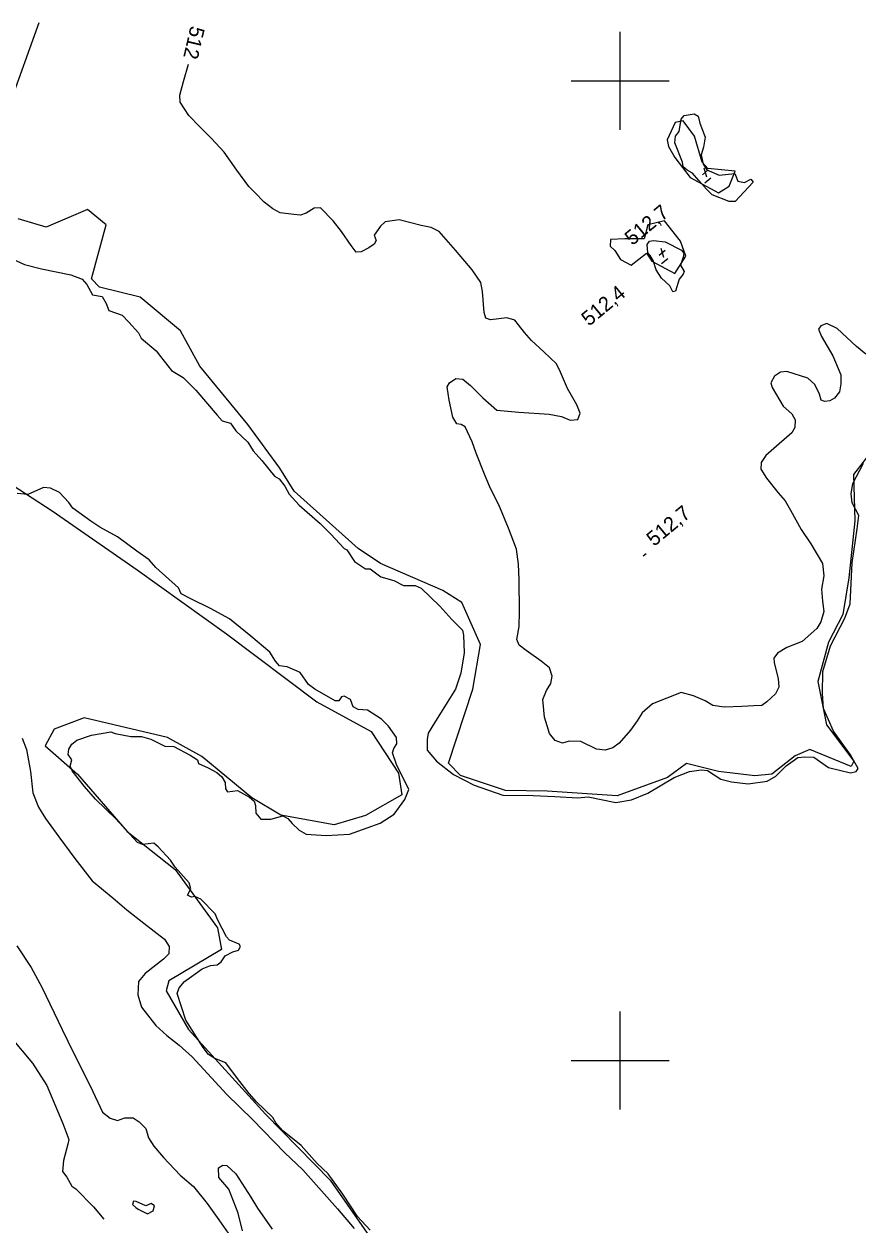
# Model space of a CAD drawing. Extents: x 347059 to 352153, y 6073752 to 6078601.
# Drawn here: x 350217.4 to 350472.8, y 6075549.6 to 6075917.4 of the extents above; entities that cross this region are included whole.
import ezdxf

# ---------------------------------------------------------------- set-up
doc = ezdxf.new("R2010")
doc.units = 0
for name, color, linetype in [('Level 2', 7, 'Continuous'), ('Level 3', 7, 'Continuous'), ('Level 4', 7, 'Continuous'), ('Level 44', 7, 'Continuous'), ('Level 61', 7, 'Continuous')]:
    doc.layers.add(name, color=color, linetype=linetype)

msp = doc.modelspace()

# ---------------------------------------------------------------- linework, layer by layer
at = {"layer": 'Level 2'}
for points in [[(350376.66, 6075817.02), (350372.8, 6075820.49), (350370.67, 6075822.86), (350368.9, 6075825.27), (350367.7, 6075826.69), (350365.29, 6075827.34), (350362.8, 6075827.12), (350360.3, 6075826.75), (350358.82, 6075827.25), (350358.3, 6075828.97), (350357.87, 6075835.49), (350357.29, 6075838.23), (350354.7, 6075842.1), (350349.51, 6075848.09), (350344.58, 6075853.77), (350342.06, 6075855.01), (350338.99, 6075855.64), (350332.3, 6075857.4), (350328.03, 6075856.75), (350326.62, 6075855.42), (350324.66, 6075852.67), (350325.25, 6075851.02), (350324.66, 6075849.98), (350322.97, 6075848.81), (350320.69, 6075847.55), (350319.16, 6075847.47), (350317.57, 6075849.5), (350314.64, 6075853.77), (350312.07, 6075857.13), (350308.24, 6075861.04), (350306.27, 6075860.99), (350303.82, 6075859.45), (350302.1, 6075858.8), (350300.08, 6075858.98), (350295.9, 6075859.49), (350293.6, 6075860.79), (350290.93, 6075862.84), (350287.97, 6075865.87), (350286.22, 6075867.63), (350282.54, 6075872.62), (350278.69, 6075878.14), (350274.79, 6075882.27), (350271.22, 6075885.87), (350267.93, 6075889.29), (350265.2, 6075893.47), (350265.15, 6075895.59), (350266.29, 6075899.79), (350267.82, 6075905.04)], [(350475.26, 6075816.21), (350472.34, 6075818.57), (350466.48, 6075824.1), (350463.27, 6075825.69), (350461.48, 6075824.98), (350460.74, 6075823.95), (350461.64, 6075821.62), (350465.09, 6075815.79), (350467.6, 6075809.97), (350467.59, 6075807.13), (350467.19, 6075804.76), (350465.66, 6075802.79), (350464.21, 6075801.97), (350462.68, 6075801.74), (350461.55, 6075802.13), (350461.04, 6075803.99), (350459.61, 6075806.95), (350457.45, 6075808.89), (350451.02, 6075810.97), (350449.05, 6075810.78), (350447.29, 6075809.55), (350446.11, 6075807.47), (350446.5, 6075806.06), (350449.96, 6075800.37), (350452.6, 6075798.03), (350453.54, 6075796.13), (350453.5, 6075793.81), (350452.58, 6075792.21), (350448.68, 6075788.77), (350444.56, 6075785.27), (350443.16, 6075783.13), (350443.07, 6075781.03), (350444.81, 6075778.33), (350448.36, 6075773.8), (350450.56, 6075771.36), (350452.15, 6075768.53), (350455.44, 6075762.57), (350458.35, 6075758.17), (350462, 6075752.11), (350462.35, 6075748.36), (350461.67, 6075744.28), (350461.96, 6075740.61), (350462.36, 6075737.45), (350461.45, 6075734.26), (350460.21, 6075732.25), (350455.69, 6075728.28), (350451.06, 6075726.49), (350448.17, 6075724.71), (350447.03, 6075723.2), (350447.2, 6075721.73), (350448.42, 6075716.97), (350448.57, 6075714.26), (350447.61, 6075712.24), (350444.88, 6075709.78), (350443.42, 6075708.67), (350440.95, 6075708.59)], [(350440.95, 6075708.59), (350437.24, 6075708.4), (350431.85, 6075708.13), (350428.34, 6075708.65), (350426.06, 6075710.09), (350422.49, 6075711.63), (350418.72, 6075712.61), (350409.89, 6075709.15), (350406.71, 6075706.43), (350405.2, 6075703.94), (350403.17, 6075701.13), (350399.73, 6075697.13), (350397.73, 6075695.7), (350395.36, 6075695.03), (350392.7, 6075695.33), (350387.95, 6075697.63), (350384.4, 6075697.72), (350382.32, 6075697.17), (350380.06, 6075697.94), (350378.35, 6075700.13), (350377.59, 6075702.45), (350376.85, 6075705.06), (350376.27, 6075710.5), (350377.43, 6075713.24), (350378.77, 6075715.46), (350379.16, 6075717.68), (350378.35, 6075720.23), (350375.82, 6075722.27), (350371.22, 6075725.5), (350369.02, 6075727.15), (350368.36, 6075728.88), (350369.04, 6075732.83), (350369.11, 6075737.34), (350369.02, 6075747.25), (350368.89, 6075752), (350368.24, 6075756.57), (350365.77, 6075762.98), (350362.78, 6075770.15), (350360.14, 6075775.34), (350358.45, 6075779.56), (350355.9, 6075785.9), (350354.65, 6075789.44), (350352.55, 6075793.99), (350351.29, 6075794.68), (350350.01, 6075794.94), (350348.79, 6075797.01), (350347.61, 6075802.21), (350346.99, 6075806.28), (350347.67, 6075807.53), (350349.66, 6075808.81), (350351.82, 6075808.62), (350354.13, 6075806.67), (350357.9, 6075802.85), (350362.25, 6075799.12), (350368.95, 6075798.46), (350378.27, 6075797.87), (350382.06, 6075797.18), (350384.65, 6075796.01), (350386.99, 6075796.24), (350387.73, 6075798.22), (350386.69, 6075800.71), (350383.9, 6075805.76), (350381.68, 6075810.76), (350380.44, 6075813.34), (350376.66, 6075817.02)], [(350216.8, 6075698.66), (350218.21, 6075695.25)], [(350218.21, 6075695.25), (350219.35, 6075688.51), (350220.06, 6075681.96), (350221.82, 6075677.5), (350224.03, 6075674.1), (350228.1, 6075668.5), (350232.96, 6075661.82), (350238.32, 6075655.01), (350244.6, 6075649.81), (350248.9, 6075646.16), (350254.11, 6075642.07), (350260.41, 6075637.16), (350261.83, 6075634.85), (350261.72, 6075632.6), (350260.14, 6075630.98), (350254.48, 6075626.58), (350252.47, 6075624.19), (350252.21, 6075620.06), (350253.37, 6075616.31), (350257.73, 6075610.69), (350261.12, 6075607.64), (350264.96, 6075604.69), (350268.9, 6075601.14), (350279.48, 6075589.61), (350287.38, 6075581.87), (350297.33, 6075571.7), (350302.81, 6075566.5), (350313.42, 6075554.6), (350318.53, 6075548.56)], [(350215.22, 6075635.1), (350219.64, 6075628.46), (350222.87, 6075622.43), (350229.11, 6075609.51), (350232.54, 6075602.3), (350237.76, 6075592.03), (350241.49, 6075584.14), (350243.74, 6075582.28), (350246.02, 6075581.65), (350248.33, 6075582.4), (350250.88, 6075582.4), (350252.67, 6075581.23), (350254.69, 6075579.17), (350255.55, 6075576.26), (350257.16, 6075573.72), (350260.09, 6075570.27), (350265.18, 6075564.89), (350269.34, 6075561.41), (350273.5, 6075556.18), (350277.09, 6075551.15), (350280.61, 6075546.05)], [(350213.2, 6075607.34), (350220.03, 6075599.13), (350224.35, 6075592.29), (350229.24, 6075580.68), (350231.1, 6075575.79), (350230.84, 6075574.36), (350229.5, 6075569.31), (350229.23, 6075565.98), (350230.47, 6075564.21), (350232.07, 6075561.53), (350233.31, 6075560.7), (350238.68, 6075555.15), (350241.87, 6075551.38)], [(350284.33, 6075547.82), (350282.99, 6075553.24), (350280.14, 6075560.58), (350277.06, 6075564.11), (350276.97, 6075567.12), (350278.32, 6075567.95), (350279.57, 6075567.79), (350282.25, 6075565.28), (350286.88, 6075558.15), (350288.95, 6075554.75), (350293.39, 6075548.3)], [(350252.38, 6075554.5), (350255.24, 6075553.04), (350256.96, 6075553.95), (350257.35, 6075555.48), (350256.35, 6075556.23), (350254.69, 6075555.52), (350251.78, 6075556.85), (350250.97, 6075556.93), (350250.63, 6075555.89), (350251.65, 6075554.93), (350252.38, 6075554.5)]]:
    msp.add_lwpolyline(points, dxfattribs=at)
at = {"layer": 'Level 3'}
for p, q in [((350425.17, 6075871.21), (350426.98, 6075872.7)), ((350425.63, 6075873.34), (350426.46, 6075870.59)), ((350425.89, 6075868.69), (350427.74, 6075870.22)), ((350412.43, 6075848.7), (350413.26, 6075845.95)), ((350411.97, 6075846.57), (350413.78, 6075848.06)), ((350412.69, 6075844.05), (350414.54, 6075845.58)), ((350407.02, 6075754.5), (350407.94, 6075755.27))]:
    msp.add_line(p, q, dxfattribs=at)
at = {"layer": 'Level 4'}
for points in [[(350419.29, 6075873.62), (350419.13, 6075875.01), (350416.77, 6075881.02), (350416.95, 6075883), (350418.08, 6075884.48), (350418.68, 6075888.25), (350419.61, 6075889.33), (350422.62, 6075889.8), (350423.88, 6075889.1), (350424.38, 6075887.01), (350426.04, 6075882.69), (350425.54, 6075879.61), (350424.82, 6075877.26), (350425.42, 6075874.42), (350426.5, 6075872.73), (350430.34, 6075871.08), (350435.13, 6075871.59), (350435.98, 6075869.26), (350438.04, 6075868.86), (350440.03, 6075869.84), (350440.77, 6075868.93), (350435.22, 6075863.01), (350433.33, 6075863.02), (350428.17, 6075865.08), (350426.47, 6075866.78), (350424.08, 6075869.42), (350422.12, 6075871.73), (350420.47, 6075872.63), (350419.29, 6075873.62)], [(350205.01, 6075849.43), (350217.55, 6075843.67), (350222.72, 6075842.35), (350231.69, 6075840.55), (350235.25, 6075839.26), (350236.63, 6075837.59), (350238.41, 6075834.43), (350241.38, 6075833.94), (350242.55, 6075831.79), (350243.39, 6075829.67), (350247.51, 6075828.16), (350249.46, 6075826.06), (350252.43, 6075822.75), (350253.27, 6075821.17), (350257.91, 6075817.28), (350259.16, 6075815.58), (350262.61, 6075811.22), (350266.17, 6075809.1)], [(350408.44, 6075847.29), (350408.23, 6075849.85), (350409.02, 6075850.82), (350410.16, 6075851.08), (350413.78, 6075850.62), (350418.73, 6075848.07), (350419.47, 6075847.17), (350419.24, 6075845.99), (350418.47, 6075843.52), (350419.61, 6075841.59), (350419.28, 6075840.78), (350418.11, 6075839.27), (350416.97, 6075835.51), (350416.13, 6075835.34), (350415.2, 6075837.22), (350412.65, 6075839.49), (350411.04, 6075842.1), (350410.07, 6075844.93), (350409.19, 6075846.47), (350408.44, 6075847.29)], [(350266.17, 6075809.1), (350270.06, 6075805.2), (350276.59, 6075797.56), (350278.08, 6075795.84), (350280.62, 6075795.15), (350282.3, 6075792.83), (350285.98, 6075789.29), (350287.6, 6075786.68), (350290.25, 6075783.65), (350294.1, 6075778.89), (350295.51, 6075778.09), (350297.25, 6075775.89), (350298.58, 6075773.36), (350301.66, 6075770), (350308.11, 6075764.45), (350311.51, 6075761.06), (350312.71, 6075759.7), (350315.44, 6075756.75), (350316.31, 6075756.34), (350318.66, 6075752.76), (350322.04, 6075750.57), (350323.4, 6075750.49), (350326.64, 6075748.11), (350330.69, 6075746.95), (350333.64, 6075745.39), (350337.23, 6075745.42), (350339.09, 6075744.63), (350344.8, 6075739.08), (350348.45, 6075735), (350351.74, 6075731.75), (350351.96, 6075730.2), (350352.24, 6075724.82), (350351.16, 6075718.54), (350349.6, 6075713.67), (350346.96, 6075709.64), (350343.13, 6075703.41), (350341.22, 6075700.23), (350340.83, 6075698.24), (350340.91, 6075695.04), (350343.75, 6075691.59), (350348.93, 6075687.51), (350355.26, 6075684.31), (350364.03, 6075681.26), (350373.35, 6075681.1), (350379.95, 6075680.78), (350387.03, 6075680.42), (350390.14, 6075680.75), (350398.7, 6075678.96), (350403.51, 6075679.8), (350408.47, 6075681.82)], [(350408.47, 6075681.82), (350416.57, 6075686.62), (350421.23, 6075688.46), (350424.81, 6075688.96), (350426.69, 6075688.79), (350430.83, 6075686.12), (350434.13, 6075685.32), (350439.17, 6075684.69), (350445.04, 6075685.51), (350447.62, 6075687.05), (350450.83, 6075690.19), (350454.4, 6075692.71), (350456.57, 6075693.01), (350459.27, 6075692.84), (350463.78, 6075689.73), (350470.53, 6075688.03), (350472.29, 6075688.45), (350472.84, 6075689.43), (350470.56, 6075693.57), (350465.34, 6075700.85), (350462.25, 6075707.72), (350461.95, 6075712.39), (350462.1, 6075719.09), (350464.4, 6075726.91), (350468.76, 6075735.46), (350470.45, 6075739.82), (350471.02, 6075752.34), (350472.55, 6075762.78), (350473.11, 6075766.88), (350471.05, 6075770.76), (350470.77, 6075773.49), (350471.28, 6075776.64), (350474.51, 6075782.9)], [(350292.69, 6075725.04), (350286.92, 6075729.93), (350280.36, 6075735.23), (350274.54, 6075738.34), (350268.47, 6075741.31), (350265.56, 6075742.91), (350264.69, 6075744.69), (350257.75, 6075750.9), (350255.75, 6075753.33), (350251.99, 6075755.97), (350246.07, 6075760.3), (350240.61, 6075763.25), (350237.85, 6075765.13), (350232.31, 6075769.1), (350231.1, 6075770.83), (350228.28, 6075773.88), (350225.56, 6075775.25), (350223.39, 6075775.41), (350218.53, 6075773.33), (350215.34, 6075773.63)], [(350260.55, 6075696.27), (350263.33, 6075696.09), (350268.28, 6075693.48), (350270.54, 6075692.03), (350270.85, 6075690.92), (350273.82, 6075689.61), (350276.41, 6075688.21), (350278.01, 6075686.82), (350279.05, 6075685.11), (350279.12, 6075683.2), (350279.73, 6075682.27), (350282.77, 6075682.61), (350286.42, 6075680.58), (350287.87, 6075679.37), (350288.33, 6075678.08), (350288.4, 6075675.72), (350289.95, 6075673.83), (350292.96, 6075673.84), (350296.72, 6075674.86), (350298.25, 6075674.1), (350299.55, 6075672.53), (350301.7, 6075670.47), (350303.86, 6075669.32), (350309.92, 6075668.92), (350317.11, 6075669.25), (350322.52, 6075671.27), (350326.52, 6075672.64), (350330.77, 6075675.44), (350334.03, 6075679.89), (350335.3, 6075682.92), (350331.44, 6075690.61), (350330.21, 6075694.2), (350330.66, 6075695.49), (350331.54, 6075696.98), (350331.47, 6075698.89), (350329.07, 6075702.34), (350326.92, 6075704.49), (350322.56, 6075707.22), (350319.79, 6075707.47), (350318.26, 6075708.32), (350317.43, 6075710.51), (350315.47, 6075711.52), (350314.63, 6075711.35), (350313.81, 6075710.14), (350312.7, 6075710.12), (350306.52, 6075713.68), (350304.55, 6075715.15), (350301.96, 6075718.75), (350297.97, 6075720.57), (350295.64, 6075720.83), (350294.41, 6075722.23), (350292.69, 6075725.04)], [(350275.8, 6075600.56), (350273.89, 6075601.77), (350272.24, 6075603.95), (350266.97, 6075612.32), (350264.3, 6075620.46), (350264.92, 6075622.26), (350266.57, 6075624.17), (350271.99, 6075628.01), (350274.48, 6075629.1), (350276.55, 6075629.24), (350277.82, 6075630.16), (350278.98, 6075632.04), (350281.36, 6075633.26), (350283.05, 6075633.77), (350283.73, 6075634.86), (350283.26, 6075635.61), (350280.37, 6075636.83), (350279.39, 6075637.83), (350276.77, 6075642.91), (350275.93, 6075644.93), (350271.52, 6075649.35), (350269.75, 6075650.21), (350268.66, 6075649.98), (350267.48, 6075650.59), (350268.52, 6075652.52), (350267.99, 6075654.43), (350263.66, 6075659.21), (350262.24, 6075661.29), (350258.5, 6075665.44), (350257.16, 6075666.52), (350253.71, 6075666.13), (350252.2, 6075666.77), (350250.92, 6075668.05), (350245.52, 6075673.93), (350239.32, 6075679.97), (350235.97, 6075683.92), (350232.16, 6075688.63), (350231.51, 6075690.14), (350232.06, 6075692.03), (350230.89, 6075693.71), (350231.16, 6075695.31), (350232.04, 6075696.88), (350233.6, 6075698.1), (350238.02, 6075699.6), (350243.97, 6075700.62), (350245.36, 6075700.12), (350250.1, 6075699.23), (350253.39, 6075699.17), (350256.21, 6075698.41), (350260.55, 6075696.27)], [(350323.45, 6075548.02), (350319.49, 6075552.25), (350315.07, 6075559.05), (350310.6, 6075565.27), (350307.23, 6075568.42), (350302.28, 6075573.95), (350296.54, 6075578.52), (350294.54, 6075580.85), (350293.58, 6075582.54), (350288.56, 6075587.34), (350286.32, 6075589.85), (350282.8, 6075594.47), (350279.26, 6075599.3), (350275.8, 6075600.56)]]:
    msp.add_lwpolyline(points, dxfattribs=at)
at = {"layer": 'Level 44'}
for points in [[(350213, 6075892.48), (350222.07, 6075917.82)], [(350416.74, 6075876.44), (350421.44, 6075870.34), (350430.07, 6075865.7), (350433.39, 6075867.72), (350435.22, 6075872.29), (350426.89, 6075873.07), (350425.1, 6075875.07), (350422.8, 6075883.03), (350419.28, 6075887.69), (350416.85, 6075887.17), (350414.37, 6075881.91), (350414.84, 6075879.87), (350416.74, 6075876.44)], [(350471.41, 6075779.38), (350471.87, 6075765.23), (350470.05, 6075747.82), (350468.16, 6075736.56), (350463.81, 6075728.1), (350460.52, 6075715.98), (350463.22, 6075702.81), (350471.52, 6075691.61), (350470.71, 6075690.03), (350458.05, 6075695.18), (350453.6, 6075693.27), (350446.49, 6075687.65), (350441.19, 6075687.15), (350430.14, 6075688.5), (350420.35, 6075690.9), (350414.52, 6075686.64), (350399.03, 6075680.97), (350377.64, 6075682.45), (350364.83, 6075682.65), (350351.12, 6075687.23), (350347.37, 6075691.05), (350354.91, 6075713.69), (350357.17, 6075727.4), (350351.45, 6075740.19), (350345.7, 6075743.88), (350326.54, 6075752.13), (350319.72, 6075756.74), (350300.1, 6075774.34), (350295.8, 6075781.38), (350285.98, 6075794.75), (350271.29, 6075812.58), (350265.36, 6075823.44), (350252.93, 6075833.76), (350240.49, 6075836.75), (350238.08, 6075839.31), (350242.56, 6075855.87), (350236.88, 6075860.57), (350224.15, 6075855.1), (350215.64, 6075857.73)], [(350400.13, 6075845.22), (350403.34, 6075843.51), (350408.05, 6075847.14), (350409.72, 6075844.74), (350416.7, 6075841.01), (350420.08, 6075846.26), (350418.45, 6075850.82), (350413.6, 6075857.1), (350408.46, 6075855.83), (350407.31, 6075851.53), (350401.38, 6075851.59), (350397.08, 6075851.33), (350396.89, 6075849.35), (350398.33, 6075847.97), (350400.13, 6075845.22)], [(350477.5, 6075787.19), (350471.41, 6075779.38)], [(350209.63, 6075778.95), (350225.99, 6075768.29), (350252.04, 6075750.27), (350279.4, 6075730.65), (350307.12, 6075709.85), (350323.72, 6075700.69), (350332.08, 6075688), (350333.1, 6075681.29), (350322, 6075675.04), (350312.35, 6075672.13), (350296.02, 6075675.13), (350287.13, 6075680.42), (350271.83, 6075693.08), (350261.33, 6075698.86), (350235.86, 6075704.86), (350226.66, 6075701.41), (350223.89, 6075696.37), (350233.8, 6075687.67), (350248.98, 6075670.06), (350263.71, 6075658.44), (350276.71, 6075640.55), (350277.91, 6075633.99), (350261.75, 6075624.42), (350260.97, 6075621.36), (350267.77, 6075609.51), (350291.34, 6075583.59), (350311.14, 6075563.32), (350337.2, 6075526.04)]]:
    msp.add_lwpolyline(points, dxfattribs=at)
at = {"layer": 'Level 61'}
for p, q in [((350400, 6075885), (350400, 6075915)), ((350385, 6075900), (350415, 6075900)), ((350400, 6075585), (350400, 6075615)), ((350385, 6075600), (350415, 6075600))]:
    msp.add_line(p, q, dxfattribs=at)

# ---------------------------------------------------------------- texts
at = {"layer": 'Level 2'}
msp.add_text('512', height=4.5, rotation=256.7568, dxfattribs=at).set_placement((350268.45, 6075916.99))
at = {"layer": 'Level 3'}
for s, rotation, p in [('  512,7', 39.57, (350401.13, 6075847.21)), ('  512,4', 39.57, (350387.86, 6075822.51)), ('512,7', 39.62, (350410.38, 6075757.22))]:
    msp.add_text(s, height=4.5, rotation=rotation, dxfattribs=at).set_placement(p)

doc.saveas('drawing.dxf')
